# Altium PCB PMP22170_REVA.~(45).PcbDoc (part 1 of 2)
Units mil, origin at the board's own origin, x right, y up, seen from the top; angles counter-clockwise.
Board outline 4950 x 3450 mil, 2 copper layers (Top Layer, Bottom Layer), stack 62 mil thick; 75 components, 28 nets, 160 pads, 77 vias.
Unrouted connection lines stored in the file: 123.
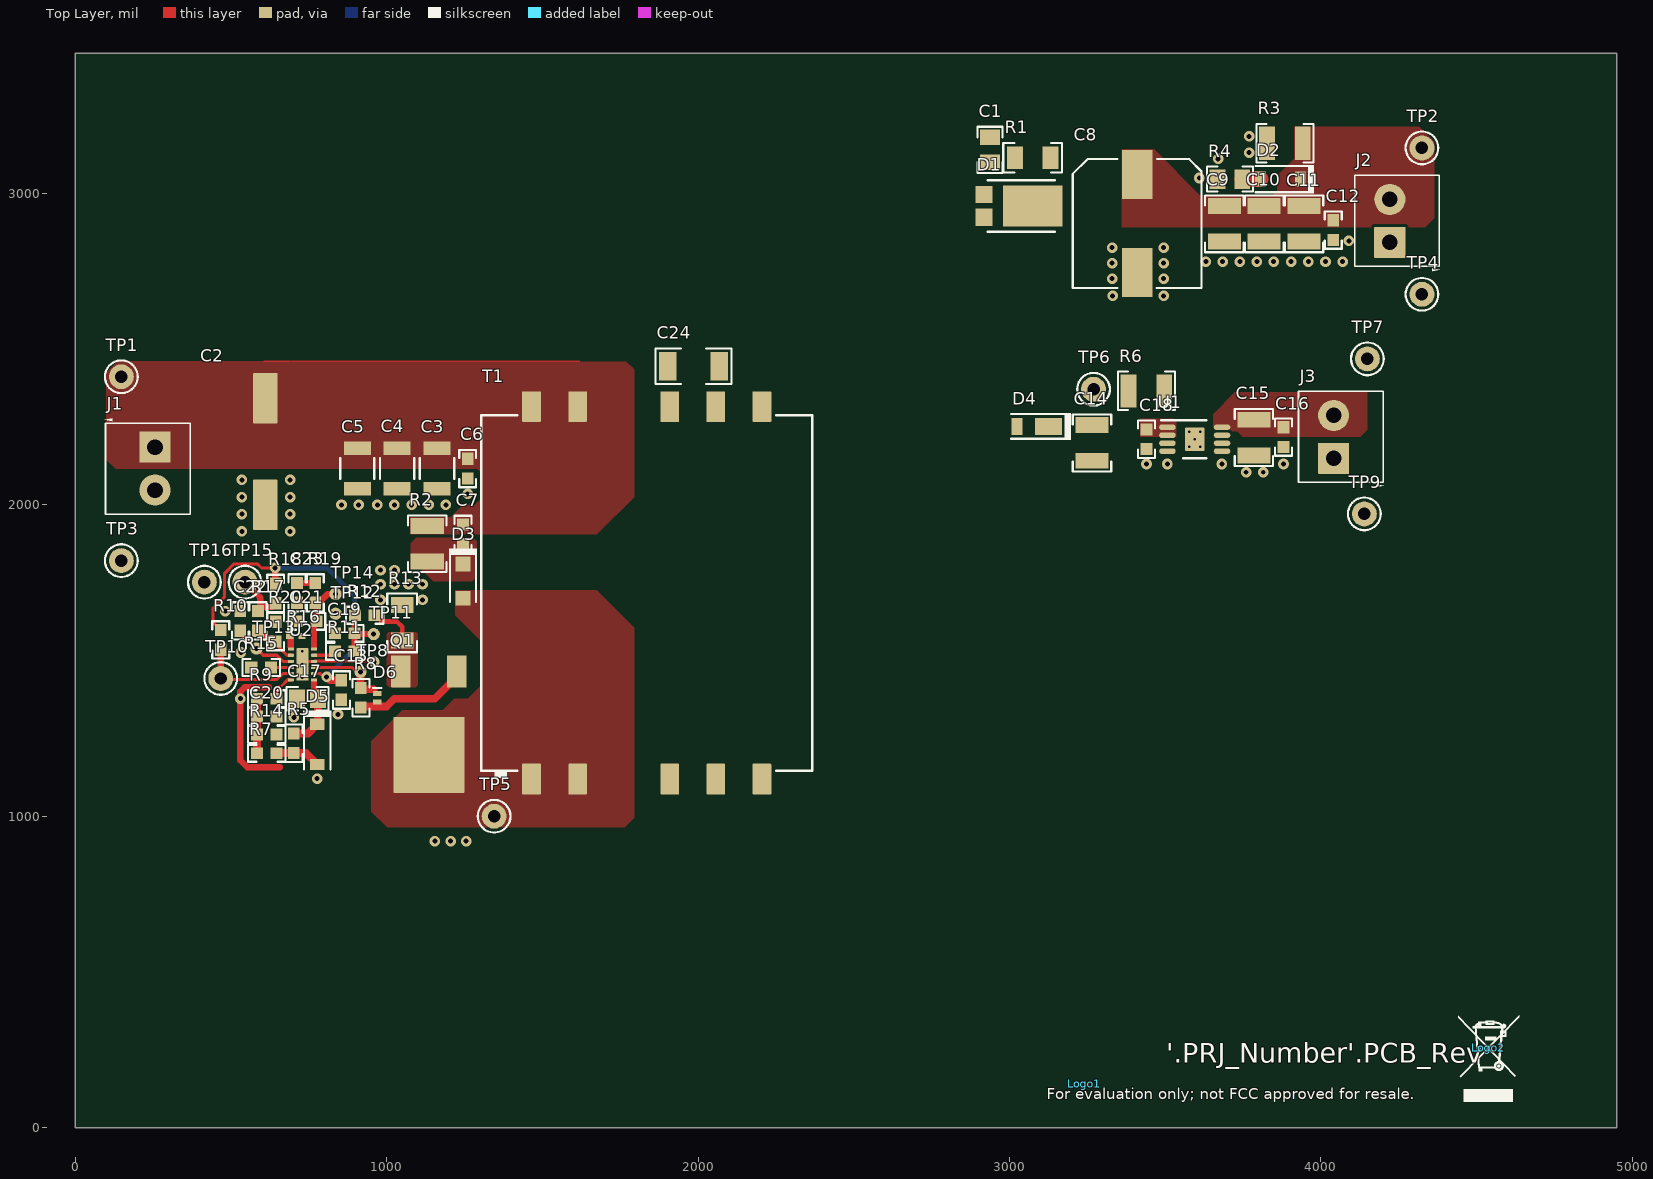
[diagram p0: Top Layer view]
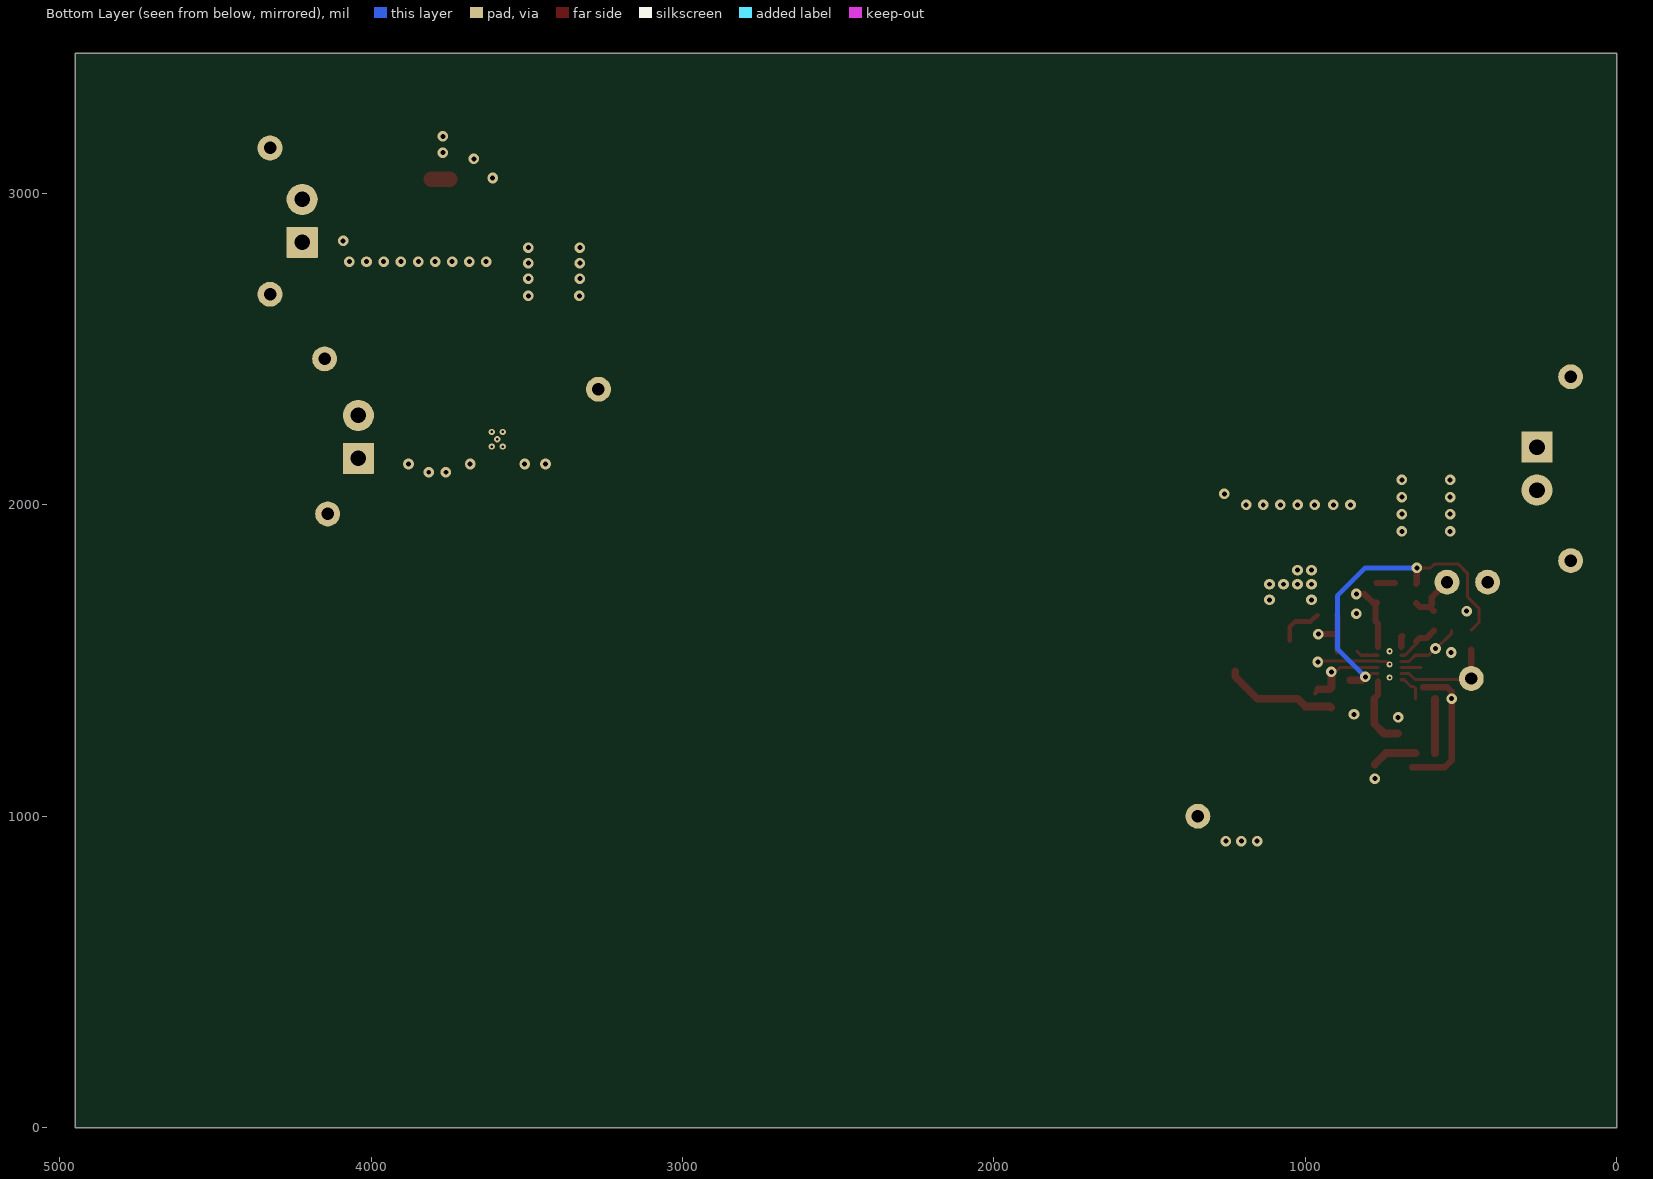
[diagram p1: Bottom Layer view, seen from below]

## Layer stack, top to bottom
Top Solder: solder mask 0.4, Solder Resist, Dk 3.5
Top Layer: signal copper 1.4
Dielectric1: core 59.2, FR-4, Dk 4.8
Bottom Layer: signal copper 1.4
Bottom Solder: solder mask 0.4, Solder Resist, Dk 3.5

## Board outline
0,0 4950,0 4950,3450 0,3450

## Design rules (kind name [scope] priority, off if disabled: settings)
AcuteAngle [All] p1: minimum=4.50000000000000E+0001 checktracksonly=FALSE
AssemblyTestPointUsage [All] p1: valid=2
BoardOutlineClearance BoardOutlineClearance_MountingHoles [OnCopper and InComponentClass('Mounting Holes')] p1: gap=39.37 ignorepadtopadclearanceinfootprint=FALSE
BoardOutlineClearance BoardOutlineClearance_Poly [OnCopper and IsPoly] p2: gap=25 ignorepadtopadclearanceinfootprint=FALSE
BoardOutlineClearance [OnCopper and Not InComponentClass('Logo') and not InComponentClass('FiducialMark') and not InRegion(1000,500,4000,800) and not InPoly] p3: gap=50 ignorepadtopadclearanceinfootprint=FALSE
Clearance Clearance_Keepouts [((IsTrack Or IsArc) And Not InPoly) And IsFree and IsKeepOut vs ((IsTrack Or IsArc) And Not InPoly) And IsFree and IsKeepOut] p1: gap=0 ignorepadtopadclearanceinfootprint=FALSE
Clearance Clearance_Poly [InPolygon] p2: gap=10 ignorepadtopadclearanceinfootprint=TRUE
Clearance Clearance_FiducialMark [IsKeepOut and InComponentClass('FiducialMark') vs IsPad and InComponentClass('FiducialMark')] p3: gap=0 ignorepadtopadclearanceinfootprint=FALSE
Clearance [All] p4: gap=7.87 ignorepadtopadclearanceinfootprint=TRUE
ComponentClearance ComponentClearance_MountingHoles_FiducialMarks [InComponentClass('Mounting Holes') vs InComponentClass('FiducialMark')] p1: gap=50 collisioncheckmode=3 verticalgap=10 showdistances=FALSE
ComponentClearance ComponentClearance_Shunt [InComponentClass('Header') vs InComponentClass('Shunt')] p2: gap=0 collisioncheckmode=3 verticalgap=0 showdistances=FALSE
ComponentClearance ComponentClearance_Logo [InComponentClass('Logo')] p3: gap=50 collisioncheckmode=3 verticalgap=10 showdistances=FALSE
ComponentClearance ComponentClearance_ScrewToNut [(HasFootprint('NY PMS 440 0025 PH')) vs (HasFootprint('Keystone_1902C'))] p4: gap=5 collisioncheckmode=3 verticalgap=10 showdistances=FALSE
ComponentClearance ComponentClearance_MountingHoles [InComponentClass('Mounting Holes')] p5: gap=250 collisioncheckmode=3 verticalgap=100000 showdistances=FALSE
ComponentClearance ComponentClearance_SmallPassives [HasFootprint('0201*') or HasFootprint('0402*') or HasFootprint('0508') or HasFootprint('0603*') or HasFootprint('0612') or HasFootprint('0805*') or HasFootprint('0815*') or HasFootprint('0830*') or HasFootprint('1206*') or HasFootprint('1210*') or HasFootprint('1808*') or HasFootprint('1812*') or HasFootprint('1825*') or HasFootprint('2010*') or HasFootprint('2220*') or HasFootprint('2225*') or HasFootprint('2512*') or HasFootprint('2728*') or HasFootprint('3518*') vs HasFootprint('0201*') or HasFootprint('0402*') or HasFootprint('0508') or HasFootprint('0603*') or HasFootprint('0612') or HasFootprint('0805*') or HasFootprint('0815*') or HasFootprint('0830*') or HasFootprint('1206*') or HasFootprint('1210*') or HasFootprint('1808*') or HasFootprint('1812*') or HasFootprint('1825*') or HasFootprint('2010*') or HasFootprint('2220*') or HasFootprint('2225*') or HasFootprint('2512*') or HasFootprint('2728*') or HasFootprint('3518*')] p6: gap=14.96 collisioncheckmode=3 verticalgap=10 showdistances=FALSE
ComponentClearance ComponentClearance_THtoSMT [IsThruComponent vs IsSMTComponent] p7: gap=30 collisioncheckmode=3 verticalgap=30 showdistances=FALSE
ComponentClearance ComponentClearance_THtoTH [IsThruComponent vs IsThruComponent] p8: gap=30 collisioncheckmode=3 verticalgap=30 showdistances=FALSE
ComponentClearance [All] p9: gap=20 collisioncheckmode=3 verticalgap=10 showdistances=FALSE
DiffPairsRouting [All] p1: maxlimit=100 minlimit=10 mostfreqgap=10 toplayer_minwidth=15 toplayer_maxwidth=15 toplayer_prefwidth=15 bottomlayer_minwidth=15 bottomlayer_maxwidth=15 bottomlayer_prefwidth=15 maxuncoupledlength=1000
FabricationTestPointUsage TestPointUsage [All] p1: valid=2 allowmultiple=FALSE
FabricationTestpoint Testpoint [All] p1: side=3 testpointundercomponent=TRUE minsize=40 maxsize=100 preferedsize=60 minholesize=0 maxholesize=40 preferedholesize=32 testpointgrid=1 allowsidetop=TRUE allowsidebottom=TRUE usegrid=TRUE gridtolerance=0.01
FanoutControl Fanout_LCC [IsLCC] p1: bgadir=Out bgaviamode=Centered fanoutstyle=Auto fanoutdirection=Alternating viagrid=1 // Fanout_LCC (Default Rule)
FanoutControl Fanout_BGA [IsBGA] p2: bgadir=Out bgaviamode=Centered fanoutstyle=Auto fanoutdirection=Alternating viagrid=1 // Fanout_BGA (Default Rule)
FanoutControl Fanout_Default [All] p4: bgadir=Out bgaviamode=Centered fanoutstyle=Auto fanoutdirection=Alternating viagrid=1 // Fanout_Default (Default Rule)
FanoutControl Fanout_Small [(CompPinCount < 5)] p5: bgadir=Out bgaviamode=Centered fanoutstyle=Auto fanoutdirection=OutThenIn viagrid=1 // Fanout_Small (Default Rule)
HoleSize [All] p1: absolutevalues=TRUE maxlimit=251 minlimit=7.87 maxpercent=80.000 minpercent=20.000
MinimumAnnularRing MinimumAnnularRing_ThermalPadVias [IsVia and InAnyComponent] p1: minimumring=5.91
MinimumAnnularRing [All] p2: minimumring=7.87
MinimumSolderMaskSliver MinimumSolderMaskSliver_Logo [InComponentClass('Logo') vs InComponentClass('Logo')] p1: minsoldermaskwidth=0.7
MinimumSolderMaskSliver [All] p2: minsoldermaskwidth=3.94
PlaneClearance [All] p1: clearance=15
PlaneConnect [All] p1: planeconnectstyle=Direct reliefexpansion=10 reliefentries=4 reliefconductorwidth=10 reliefairgap=10
PolygonConnect [All] p1: connectstyle=Direct reliefconductorwidth=10 reliefentries=4 polygonreliefangle="90 Angle" airgapwidth=10
RoutingVias ThermalPadVias [IsVia and InAnyComponent] p1: holewidth=7.87 width=19.68 viastyle="Through Hole" minholewidth=7.87 minwidth=19.68 maxholewidth=12.99 maxwidth=23.62
RoutingVias [All] p2: holewidth=16 width=34 viastyle="Through Hole" minholewidth=7.87 minwidth=26 maxholewidth=40 maxwidth=65
SilkToBoardRegionClearance [Not ((IsComment or IsDesignator) And (Hide <> 'False')) and not InRegion(1000,500,4000,800)] p1:
SilkToSilkClearance SilkToSilkClearance_Pb-FreeLogo [(HasFootprint('Pb-Free_Overlay_Medium') OR HasFootprint('Pb-Free_Overlay_Small')) vs (HasFootprint('Pb-Free_Overlay_Medium') OR HasFootprint('Pb-Free_Overlay_Small'))] p1: silktosilkclearance=0
SilkToSilkClearance [All] p2: silktosilkclearance=0
SilkToSolderMaskClearance SilkToComponentPadClearance [(IsPad or IsFill or IsRegion) and InAnycomponent] p1: minsilkscreentomaskgap=5 clearancetoexposedcopper=TRUE
SilkToSolderMaskClearance "Silk to Solder Mask Opening" [All] p2: minsilkscreentomaskgap=0 clearancetoexposedcopper=FALSE
SolderMaskExpansion [All] p1: expansion=1.97
UnRoutedNet [All] p1: checkbadconnections=TRUE
Width [All] p1: maxlimit=100 minlimit=6 preferedwidth=10 checkconnectedcopper=TRUE
13 further rules are at their usual default settings.

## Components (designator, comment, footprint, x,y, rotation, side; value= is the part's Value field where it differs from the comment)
C1 "Capacitor" 0805_HV 2937.52,3140.12 r270 top value=100pF
C2 "EEH-ZS1H221V" FP-EEHZS1H221P_RADIAL_SMD-MFG 610.24,2171.35 r90 top
C3 "UMK325AB7106KMHT" 1210_280 1161.42,2116.35 r270 top value=10uF
C4 "UMK325AB7106KMHT" 1210_280 1033.46,2116.35 r270 top value=10uF
C5 "UMK325AB7106KMHT" 1210_280 905.51,2116.35 r270 top value=10uF
C6 "Capacitor" 0603 1259.84,2116.35 r270 top value=0.1uF
C7 "Capacitor" 0603 1245,1905 r270 top value=0.1uF
C8 "EEHZC1E331P" SM_RADIAL_10BMM 3409.96,2903.53 r270 top value=330uF
C9 "TMK325B7226KMHT" 1210_270 3690,2902.2 r270 top value=22uF
C10 "TMK325B7226KMHT" 1210_270 3817.95,2902.2 r270 top value=22uF
C11 "TMK325B7226KMHT" 1210_270 3945.91,2902.38 r270 top value=22uF
C12 "Capacitor" 0603 4040,2882.26 r270 top value=0.1uF
C13 "GCM188R71E105KA64D" 0603 854.45,1405.37 r270 top value=1uF
C14 "Capacitor" 1210_270 3265,2198.78 r270 top value=22uF
C15 "Capacitor" 1210_270 3785,2216.22 r270 top value=47uF
C16 "Capacitor" 0603 3880,2217.48 r270 top value=0.1uF
C17 "Capacitor" 0805 745.3,1377.3 r180 top value=1uF
C18 "Capacitor" 0603 3440,2210.79 r270 top value=0.1uF
C19 "Capacitor" 0603 865.22,1587.34 r180 top value=1000pF
C20 "Capacitor" 0603 614.79,1320.34 r0 top value=10pF
C21 "CGA3E2X7R2A222K080AA" 0603 742.84,1625.84 r180 top value=2200pF
C22 "Capacitor" 0603 529.91,1627.22 r90 top value=0.1uF
C23 "CGA3E3X7R1H334K080AB" 0603 711.83,1717.34 r270 top value=0.33uF
C24 "Capacitor" 1808 1985,2445 r180 top value=1000pF
D1 "PDS4200HQ-13" POWERDI5 2996.22,2959.8 r0 top value=200V
D2 "MMSZ5240B-7-F" SOD-123 3870.59,3046.22 r180 top value=10V
D3 "DIODE_SCHOTTKY" SOD-123W 1245,1755 r270 top value=100V
D4 "DFLS1200Q-7" PowerDI123 3074.8,2251.93 r180 top value=200V
D5 "SD103AW-7-F" SOD-123 776.83,1230.84 r270 top value=40V
D6 "DIODE_SCHOTTKY" X1-DFN1006-2 969.37,1380.37 r270 top value=30V
J1 "Receptacle_2x1" TERM_BLK_ED555-2DS 255.91,2185.24 r270 top
J2 "Receptacle_2x1" TERM_BLK_ED555-2DS 4221.5,2842.89 r90 top
J3 "Receptacle_2x1" TERM_BLK_ED555-2DS 4041.18,2149.27 r90 top
Logo1 "FCC disclaimer" FCC_disclaimer 3240,140 r0 top
Logo2 "WEEE logo" WEEE_Minimum 4537.4,255.91 r0 top
Q1 "IPD60N10S4L12ATMA1" DPAK 1135.35,1331.12 r270 top value=100V
R1 "CRCW1206100RFKEAHP" 1206 3074.61,3114.53 r0 top value=100
R2 "ERJ14NF1001U" 1210 1130,1875 r90 top value=1.00k
R3 "ERJ14NF1001U" 1210 3884.76,3161.22 r0 top value=1.00k
R4 "CRCW080580R6FKEA" 0805_HV 3708.19,3046.22 r0 top value=80.6
R5 "Resistor" 0603 701.83,1234.15 r270 top value=0
R6 "ERJ14NF1001U" 1210 3440,2366.22 r180 top value=1.00k
R7 "CRCW0603100KFKEA" 0603 614.79,1202.3 r0 top value=100k
R8 "Resistor" 0603 917.13,1380.37 r90 top value=10.0
R9 "CRCW060371K5FKEA" 0603 614.79,1377.34 r0 top value=71.5k
R10 "CRCW060310K0FKEA" 0603 466.83,1566.19 r270 top value=10.0k
R11 "Resistor" 0603 865.22,1529.66 r0 top value=0
R12 "Resistor" 0603 929.45,1645.37 r0 top value=100
R13 "ERJ-8BWFR010V" 1206 1049.45,1621.18 r270 top value=0.010
R14 "CRCW060324K9FKEA" 0603 614.79,1262.34 r180 top value=24.9k
R15 "CRCW060373K2FKEA" 0603 596.83,1477.49 r0 top value=73.2k
R16 "CRCW04020000Z0ED" 0402L 708.39,1578.99 r180 top value=0
R17 "Resistor" 0603 586.83,1627.34 r270 top value=6.04k
R18 "CRCW060320R0FKEA" 0603 643.33,1715.39 r90 top value=20.0
R19 "CRCW06033K01FKEA" 0603 770.34,1717.34 r270 top value=3.01k
R20 "CRCW06031K00FKEA" 0603 643.33,1592.77 r270 top value=1.00k
T1 "750315862" Wurth_750315862 1835,1717.37 r90 top value=45uH
TP1 "5000" Keystone5000 147.64,2411.42 r90 top
TP2 "5000" Keystone5000 4324.76,3146.22 r90 top
TP3 "5001" Keystone5001 147.64,1820.87 r90 top
TP4 "5001" Keystone5001 4324.76,2676.22 r90 top
TP5 "5002" Keystone5002 1345,1000 r0 top
TP6 "5000" Keystone5000 3270,2371.22 r0 top
TP7 "5000" Keystone5000 4149.45,2468.82 r90 top
TP8 "TP_SM_1MM" TP_SM_1MM 915.97,1463.91 r90 top
TP9 "5001" Keystone5001 4139.61,1970.91 r90 top
TP10 "5000" Keystone5000 466.83,1442.34 r0 top
TP11 "TP_SM_1MM" TP_SM_1MM 958.29,1584.89 r270 top
TP12 "TP_SM_1MM" TP_SM_1MM 835.75,1650.37 r270 top
TP13 "TP_SM_1MM" TP_SM_1MM 581.83,1538.63 r0 top
TP14 "TP_SM_1MM" TP_SM_1MM 835.75,1713.7 r0 top
TP15 "5003" Keystone5003 544.9,1751.78 r0 top
TP16 "5001" Keystone5001 414.45,1751.78 r0 top
U1 "TPS7B8250QDGNRQ1" DGN0008D_N 3595,2210.79 r0 top
U2 "LM5155QDSSTQ1" DSS0012C 729.43,1487.34 r180 top

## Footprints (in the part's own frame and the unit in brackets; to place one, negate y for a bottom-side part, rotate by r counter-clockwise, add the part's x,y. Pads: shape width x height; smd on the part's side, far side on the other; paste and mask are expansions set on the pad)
0402L [mm] "0402 from SM-752 data"
  rect 0.6x0.5 smd: 1(-0.5,0) 2(0.5,0)
  body extent -0.55,-0.3 0.55,0.3, height 0.6
0603 [mm] "0603 from SM-752 data"
  rect 1x0.95 smd: 1(-0.8,0) 2(0.8,0)
  silkscreen extent -1.52,-0.69 1.52,0.69, body extent -0.87,-0.47 0.87,0.47, height 1
0805 [mm] "0805 from SM-752 data"
  rect 1.3x1.5 smd: 1(-0.85,0) 2(0.85,0)
  silkscreen extent -1.72,-0.97 1.72,0.97, body extent -1.1,-0.72 1.1,0.72, height 1.45
0805_HV [mil] "0805 with 30mil clearance between pads"
  rect 50x63 smd: 1(-40,0) 2(40,0)
  silkscreen extent -74,-40 74,40, body extent -43,-29 43,29, height 57
1206 [mm] "1206 from SM-752 data"
  rect 1.3x1.85 smd: 1(-1.45,0) 2(1.45,0)
  silkscreen extent -2.4,-1.21 2.4,1.21, body extent -1.7,-0.9 1.7,0.9, height 1.35
1210 [mm] "1210 from SM-752 data"
  rect 1.3x2.7 smd: 1(-1.45,0) 2(1.45,0)
  silkscreen extent -2.32,-1.57 2.32,1.57, body extent -1.7,-1.35 1.7,1.35, height 1.35
1210_270 [mm] "1210"
  rect 1.3x2.7 smd: 1(-1.45,0) 2(1.45,0)
  silkscreen extent -2.32,-1.57 2.32,1.57, body extent -1.7,-1.35 1.7,1.35, height 2.7
1210_280 [mm] "SMD, 2-Leads, Body 3.6x2.8mm, Height 2.8mm"
  rect 1.1x2.2 smd: 1(-1.65,0) 2(1.65,0)
  silkscreen extent -0.84,-1.4 0.84,1.4, body extent -1.8,-1.4 1.8,1.4, height 2.8
1808 [mm] "Chip Capacitor, Body 4.6x2.0mm, IPC Medium Density"
  rect 1.4x2.3 smd: 1(-2.1,0) 2(2.1,0)
  silkscreen extent -3.1,-1.45 3.1,1.45, body extent -2.47,-1.2 2.47,1.2, height 2.03
DGN0008D_N [mm] "TSOP, 8-Leads, Body 3x3mm, Pitch 0.65mm, Thermal Pad 1.89x1.57mm, IPC Medium Density"
  rrect100% 1.35x0.45 smd: 1(-2.225,0.975) 2(-2.225,0.325) 3(-2.225,-0.325) 4(-2.225,-0.975) 5(2.225,-0.975) 6(2.225,-0.325) 7(2.225,0.325) 8(2.225,0.975)
  rrect6% 1.57x1.89 smd: 9(0,0)
  silkscreen extent -2.73,-1.55 0.95,1.55, body extent -2.46,-1.5 2.46,1.5, height 1.1
DPAK [mm] "D-PAK, 3-Pads, Body 6.22x6.73mm (max), TO-252AA using nominal STEP model"
  rrect6% 2.6x1.6 smd: 1(-3.4,2.28) 3(-3.4,-2.28)
  rrect2% 6.2x5.8 smd paste-3: 2(3.4,0)
  body extent -3.86,-3.29 5.84,3.29, height 2.48
DSS0012C [mm] "WSON-12"
  rrect40% 0.5x0.25 smd: 1(-0.95,1.25) 2(-0.95,0.75) 3(-0.95,0.25) 4(-0.95,-0.25) 5(-0.95,-0.75) 6(-0.95,-1.25) 7(0.95,-1.25) 8(0.95,-0.75) 9(0.95,-0.25) 10(0.95,0.25) 11(0.95,0.75) 12(0.95,1.25)
  rrect11% 0.95x1.17 on Top Paste: 13(0,0.685) 13(0,-0.685)
  rrect11% 1x2.65 smd paste-0.5: 13(0,0)
  body extent -1,-1.5 1,1.5, height 0.81
FCC_disclaimer [mil]
FP-EEHZS1H221P_RADIAL_SMD-MFG [mm]
  rrect5% 4.1x2 smd paste+0 mask+0: 1(-4.35,0) 2(4.35,0)
  body extent -6.65,-5.5 6.65,5.5, height 0.25
Keystone5000 [mil] "For Keystone 500x miniature loop terminals"
  round 80 hole 40: 1(0,0)
  silkscreen extent -52,-52 52,52, body extent -49,-49 49,49, height 182
Keystone5001 [mil] "For Keystone 500x miniature loop terminals"
  round 80 hole 40: 1(0,0)
  silkscreen extent -52,-52 52,52, body extent -49,-49 49,49, height 182
Keystone5002 [mil] "For Keystone 500x miniature loop terminals"
  round 80 hole 40: 1(0,0)
  silkscreen extent -52,-52 52,52, body extent -49,-49 49,49, height 182
Keystone5003 [mil] "For Keystone 500x miniature loop terminals"
  round 80 hole 40: 1(0,0)
  silkscreen extent -52,-52 52,52, body extent -49,-49 49,49, height 182
POWERDI5 [mm] "Diodes Inc recommended land pattern, ap02001.pdf rev 60"
  rect 1.4x1.39 smd: 1(-1.991,0.92) 2(-1.991,-0.92)
  rect 4.86x3.36 smd: 3(1.991,0)
  silkscreen extent -1.7,-2.1 3.8,2.1, body extent -2.27,-2.03 4.33,2.03, height 1.17
PowerDI123 [mm] "Diodes Inc recommended land pattern, document number DS30628 Rev. 6-2"
  rect 2.2x1.4 smd: 1(-1.275,0)
  rect 0.9x1.4 smd: 2(1.275,0)
  silkscreen extent -3.1,-1.09 1.76,1.09, body extent -2.38,-0.97 1.52,0.96, height 1
SM_RADIAL_10BMM [mm] "Nichicon 10x10"
  rect 4x2.5 smd: 1(-4,0) 2(4,0)
  silkscreen extent -5.25,-5.25 5.25,5.25, body extent -5.25,-5.25 5.25,5.25, height 10.5
SOD-123 [mm] "On Semi recommended land pattern"
  rect 0.915x1.22 smd: 1(-1.637,0) 2(1.637,0)
  silkscreen extent -2.74,-1.17 2.03,1.17, body extent -1.93,-0.9 1.93,0.9, height 1.35
SOD-123W [mm] "NXP recommended land pattern"
  rect 1.2x1.2 smd paste-0.05: 1(-1.4,0) 2(1.4,0)
  silkscreen extent -2.64,-1.14 1.68,1.14, body extent -1.85,-0.95 1.85,0.95, height 1.1
TERM_BLK_ED555-2DS [mil]
  rrect4% 100x100 hole 50: 1(0,0)
  round 100 hole 50: 2(138,0)
  silkscreen extent -93,-161 215,113, body extent -69,-150 207,106, height 323
TP_SM_1MM [mm] "1mm Test Point, SMT"
  round 1 smd paste-0.5: 1(0,0)
WEEE_Minimum [mil] "WEEElie bin"
  silkscreen extent -95,-172 99,104
Wurth_750315862 [mm] "SMD, 12-Leads, Body 32.45x27.03mm, Pitch 3.76mm"
  rrect7% 2.5x1.52 smd: 1(-15.19,9.4) 2(-15.19,5.64) 4(-15.19,-1.88) 5(-15.19,-5.64) 6(-15.19,-9.4) 7(15.19,-9.4) 8(15.19,-5.64) 9(15.19,-1.88) 11(15.19,5.64) 12(15.19,9.4)
  silkscreen extent -15.1,-13.51 14.5,13.51, body extent -16.25,-13.51 16.25,13.51, height 13.98
X1-DFN1006-2 [mm] "DIODES, INC"
  rect 0.4x0.7 smd: 1(-0.35,0) 2(0.35,0)
  silkscreen extent -0.8,-0.35 -0.8,0.35, body extent -0.54,-0.34 0.54,0.34, height 0.53

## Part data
C1: library part CMP-0008236-2, "CAP, CERM, 100 pF, 250 V, +/- 5%, C0G/NP0, 0805", Cap_Case=0805, Manufacturer=MuRata, PartNumber=GRM21A5C2E101JW01D, Supplier Part Number 1=490-5542-1-ND, TempCo=C0G/NP0, Tolerance_%=5%, Value1=Unknown, Value2=250V, ValueDisplayed=100pF
C2: library part CMP-0087071-1, "220µF 50V Aluminum Polymer Capacitor Radial, Can - SMD 13 mOhm 4000 Hrs @ 125°C", Manufacturer=Panasonic, Tolerance_%=20%
C3 C4 C5: library part CMP-0009258-2, "CAP, CERM, 10 uF, 50 V, +/- 10%, X7R, AEC-Q200 Grade 1, 1210", Cap_Case=1210, Manufacturer="Taiyo Yuden", Supplier Part Number 1=587-4326-1-ND, TempCo=X7R, Tolerance_%=10%, Value1=Unknown, Value2=50V, ValueDisplayed=10uF
C6 C7 C12: library part CMP-0007144-4, "CAP, CERM, 0.1 uF, 50 V, +/- 10%, X7R, 0603", Cap_Case=0603, Manufacturer=MuRata, PartNumber=GCM188R71H104KA57D, Supplier Part Number 1=490-4779-1-ND, TempCo=X7R, Tolerance_%=10%, Value1="0.02 ohm", Value2=50V, ValueDisplayed=0.1uF
C8: library part CMP-0012593-3, "CAP, Polymer Hybrid, 330 uF, 25 V, +/- 20%, 20 mohm, 10x10 SMD", Manufacturer=Panasonic, Supplier Part Number 1=P15459CT-ND, Tolerance_%=20%, Value1="20 ohm", Value2=25V, ValueDisplayed=330uF
C9 C10 C11: library part CMP-0009255-2, "CAP, CERM, 22 uF, 25 V, +/- 10%, X7R, AEC-Q200 Grade 1, 1210", Cap_Case=1210, Manufacturer="Taiyo Yuden", Supplier Part Number 1=587-4337-1-ND, TempCo=X7R, Tolerance_%=10%, Value1=Unknown, Value2=25V, ValueDisplayed=22uF
C13: library part CMP-0007139-4, "CAP, CERM, 1 uF, 25 V, +/- 10%, X7R, AEC-Q200 Grade 1, 0603", Cap_Case=0603, Manufacturer=MuRata, Supplier Part Number 1=490-10673-1-ND, TempCo=X7R, Tolerance_%=10%, Value1=Unknown, Value2=25V, ValueDisplayed=1uF
C14: library part CMP-0009224-2, "CAP, CERM, 22 uF, 25 V, +/- 10%, X7R, 1210", Cap_Case=1210, Manufacturer=MuRata, PartNumber=GRM32ER71E226KE15L, Supplier Part Number 1=490-5313-1-ND, TempCo=X7R, Tolerance_%=10%, Value1=Unknown, Value2=25V, ValueDisplayed=22uF
C15: library part CMP-0009220-2, "CAP, CERM, 47 uF, 10 V, +/- 10%, X7R, 1210", Cap_Case=1210, Manufacturer=MuRata, PartNumber=GRM32ER71A476KE15L, Supplier Part Number 1=490-5312-1-ND, TempCo=X7R, Tolerance_%=10%, Value1=Unknown, Value2=10V, ValueDisplayed=47uF
C16 C18 C22: library part CMP-0007378-5, "CAP, CERM, 0.1 uF, 16 V, +/- 10%, X7R, 0603", Cap_Case=0603, Manufacturer=MuRata, PartNumber=GRM188R71C104KA01D, Supplier Part Number 1=490-1532-1-ND, TempCo=X7R, Tolerance_%=10%, Value1=Unknown, Value2=16V, ValueDisplayed=0.1uF
C17: library part CMP-0008350-2, "CAP, CERM, 1 uF, 50 V, +/- 10%, X7R, 0805", Cap_Case=0805, Manufacturer=MuRata, PartNumber=GRM21BR71H105KA12L, Supplier Part Number 1=490-4736-1-ND, TempCo=X7R, Tolerance_%=10%, Value1=Unknown, Value2=50V, ValueDisplayed=1uF
C19: library part CMP-0007402-4, "CAP, CERM, 1000 pF, 25 V, +/- 10%, X7R, 0603", Cap_Case=0603, Manufacturer=MuRata, PartNumber=GRM188R71E102KA01D, Supplier Part Number 1=GRM188R71E102KA01D-ND, TempCo=X7R, Tolerance_%=10%, Value1=Unknown, Value2=25V, ValueDisplayed=1000pF
C20: library part CMP-0007170-4, "CAP, CERM, 10 pF, 50 V, +/- 5%, C0G/NP0, 0603", Cap_Case=0603, Manufacturer=MuRata, PartNumber=GRM1885C1H100JA01D, Supplier Part Number 1=490-1403-1-ND, TempCo=C0G/NP0, Tolerance_%=5%, Value1=Unknown, Value2=50V, ValueDisplayed=10pF
C21: library part CMP-0007085-4, "CAP, CERM, 2200 pF, 100 V, +/- 10%, X7R, AEC-Q200 Grade 1, 0603", Cap_Case=0603, Manufacturer=TDK, Supplier Part Number 1=445-5808-1-ND, TempCo=X7R, Tolerance_%=10%, Value1="0.923948 ohm", Value2=100V, ValueDisplayed=2200pF
C23: library part CMP-0007095-4, "CAP, CERM, 0.33 uF, 50 V, +/- 10%, X7R, AEC-Q200 Grade 1, 0603", Cap_Case=0603, Manufacturer=TDK, Supplier Part Number 1=445-174426-1-ND, TempCo=X7R, Tolerance_%=10%, Value1="0.01584 ohm", Value2=50V, ValueDisplayed=0.33uF
C24: library part CMP-0009436-2, "CAP, CERM, 1000 pF, 2000 V, +/- 10%, X7R, 1808", Cap_Case=1808, Manufacturer=MuRata, PartNumber=GR442QR73D102KW01L, Supplier Part Number 1=490-8145-1-ND, TempCo=X7R, Tolerance_%=10%, Value1=Unknown, Value2=2000V, ValueDisplayed=1000pF
D1: library part CMP-0081019-2, "Diode, Schottky, 200 V, 4 A, AEC-Q101, PowerDI5", Manufacturer="Diodes Inc.", Value1=4A, Value2=0.84V
D2: library part CMP-0005749-3, "Diode, Zener, 10 V, 500 mW, SOD-123", Manufacturer="Diodes Inc.", Power_W=500mW, Value1=0.5W
D3: library part CMP-0028782-2, "Diode, Schottky, 100 V, 1 A, AEC-Q101, SOD-123W", Manufacturer=Nexperia, PartNumber=PMEG10010ELRX, Value1=1A, Value2=0.77V
D4: library part CMP-0028517-2, "Diode, Schottky, 200 V, 1 A, PowerDI123", Manufacturer="Diodes Inc.", Value1=1A, Value2=0.85V
D5: library part CMP-0028543-1, "Diode, Schottky, 40 V, 0.35 A, SOD-123", Manufacturer="Diodes Inc.", Supplier Part Number 1=SD103-AWDICT-ND, Value1=0.35A, Value2=0.55V
D6: library part CMP-0076931-2, "Diode, Schottky, 30 V, 0.2 A, 1.00x0.50x0.60mm", Manufacturer="Diodes Inc.", PartNumber=BAT54LP-7, Value1=0.2A, Value2=1V
J1 J2 J3: library part CMP-0074913-1, "Terminal Block, 3.5mm Pitch, 2x1, TH", Color=Grey, Current_A=6A, Manufacturer="On-Shore Technology", PartNumber=ED555/2DS, Supplier Part Number 1=ED1514-ND, Voltage_V=150V
Logo1: library part CMP-0074847-1, "FCC_disclaimer"
Logo2: library part CMP-0074769-1
Q1: library part CMP-0080670-2, "MOSFET, N-CH, 100 V, 60 A, AEC-Q101, DPAK", Alternate Manufacturer=None, Manufacturer="Infineon Technologies", Supplier Part Number 1=IPD60N10S4L12ATMA1CT-ND, Value1="0.015 ohm", Value2="38 nC"
R1: library part CMP-0016570-3, "RES, 100, 1%, 0.5 W, AEC-Q200 Grade 0, 1206", Manufacturer=Vishay-Dale, Power_W=500mW, Supplier Part Number 1=541-100UCT-ND, TempCo="100 ppm/C", Tolerance_%=1%, Value2=0.5W, Value_Code=100R, ValueDisplayed=100
R2 R3 R6: library part CMP-0015030-3, "RES, 1.00 k, 1%, 0.5 W, AEC-Q200 Grade 0, 1210", Manufacturer=Panasonic, Power_W=500mW, Supplier Part Number 1=P1.00KAACT-ND, TempCo="100 ppm/C", Tolerance_%=1%, Value2=0.5W, Value_Code=1k00, ValueDisplayed=1.00k
R4: library part CMP-0021452-3, "RES, 80.6, 1%, 0.125 W, AEC-Q200 Grade 0, 0805", Manufacturer=Vishay-Dale, Power_W=125mW, Supplier Part Number 1=541-80.6CCT-ND, TempCo="100 ppm/C", Tolerance_%=1%, Value2=0.125W, Value_Code=80R6, ValueDisplayed=80.6
R5 R11: library part CMP-0025697-4, "RES, 0, 5%, 0.1 W, AEC-Q200 Grade 0, 0603", Manufacturer=Vishay-Dale, PartNumber=CRCW06030000Z0EA, Power_W=100mW, Supplier Part Number 1=541-0.0GCT-ND, TempCo="200 ppm/C", Tolerance_%=5%, Value2=0.1W, Value_Code=0000, ValueDisplayed=0
R7: library part CMP-0021990-4, "RES, 100 k, 1%, 0.1 W, AEC-Q200 Grade 0, 0603", Manufacturer=Vishay-Dale, Power_W=100mW, Supplier Part Number 1=541-100KHCT-ND, TempCo="100 ppm/C", Tolerance_%=1%, Value2=0.1W, Value_Code=100k
R8: library part CMP-0022003-4, "RES, 10.0, 1%, 0.1 W, AEC-Q200 Grade 0, 0603", Manufacturer=Vishay-Dale, PartNumber=CRCW060310R0FKEA, Power_W=100mW, Supplier Part Number 1=541-10.0HCT-ND, TempCo="100 ppm/C", Tolerance_%=1%, Value2=0.1W, Value_Code=10R0, ValueDisplayed=10.0
R9: library part CMP-0022581-4, "RES, 71.5 k, 1%, 0.1 W, AEC-Q200 Grade 0, 0603", Manufacturer=Vishay-Dale, Power_W=100mW, Supplier Part Number 1=541-71.5KHCT-ND, TempCo="100 ppm/C", Tolerance_%=1%, Value2=0.1W, Value_Code=71k5, ValueDisplayed=71.5k
R10: library part CMP-0021998-4, "RES, 10.0 k, 1%, 0.1 W, AEC-Q200 Grade 0, 0603", Manufacturer=Vishay-Dale, Power_W=100mW, Supplier Part Number 1=541-10.0KHCT-ND, TempCo="100 ppm/C", Tolerance_%=1%, Value2=0.1W, Value_Code=10k0, ValueDisplayed=10.0k
R12: library part CMP-0021991-4, "RES, 100, 1%, 0.1 W, AEC-Q200 Grade 0, 0603", Manufacturer=Vishay-Dale, PartNumber=CRCW0603100RFKEA, Power_W=100mW, Supplier Part Number 1=541-100HCT-ND, TempCo="100 ppm/C", Tolerance_%=1%, Value2=0.1W, Value_Code=100R, ValueDisplayed=100
R13: library part CMP-0750151-1, "RES, 0.010, 1%, 1 W, AEC-Q200 Grade 0, 1206", Manufacturer=Panasonic, Power_W=1W, TempCo="200 ppm/C", Tolerance_%=1%, Value_Code=R010, ValueDisplayed=0.010
R14: library part CMP-0022237-4, "RES, 24.9 k, 1%, 0.1 W, AEC-Q200 Grade 0, 0603", Manufacturer=Vishay-Dale, Power_W=100mW, Supplier Part Number 1=541-24.9KHCT-ND, TempCo="100 ppm/C", Tolerance_%=1%, Value2=0.1W, Value_Code=24k9, ValueDisplayed=24.9k
R15: library part CMP-0022585-4, "RES, 73.2 k, 1%, 0.1 W, AEC-Q200 Grade 0, 0603", Manufacturer=Vishay-Dale, Power_W=100mW, Supplier Part Number 1=541-73.2KHCT-ND, TempCo="100 ppm/C", Tolerance_%=1%, Value2=0.1W, Value_Code=73k2, ValueDisplayed=73.2k
R16: library part CMP-0026822-3, "RES, 0, 5%, 0.063 W, AEC-Q200 Grade 0, 0402", Manufacturer=Vishay-Dale, Power_W=63mW, Supplier Part Number 1=541-0.0JCT-ND, TempCo="200 ppm/C", Tolerance_%=5%, Value2=0.063W, Value_Code=0000, ValueDisplayed=0
R17: library part CMP-0022558-4, "RES, 6.04 k, 1%, 0.1 W, AEC-Q200 Grade 0, 0603", Manufacturer=Vishay-Dale, PartNumber=CRCW06036K04FKEA, Power_W=100mW, Supplier Part Number 1=541-6.04KHCT-ND, TempCo="100 ppm/C", Tolerance_%=1%, Value2=0.1W, Value_Code=6k04, ValueDisplayed=6.04k
R18: library part CMP-0022206-4, "RES, 20.0, 1%, 0.1 W, AEC-Q200 Grade 0, 0603", Manufacturer=Vishay-Dale, Power_W=100mW, Supplier Part Number 1=541-20.0HCT-ND, TempCo="100 ppm/C", Tolerance_%=1%, Value2=0.1W, Value_Code=20R0, ValueDisplayed=20.0
R19: library part CMP-0022371-4, "RES, 3.01 k, 1%, 0.1 W, AEC-Q200 Grade 0, 0603", Manufacturer=Vishay-Dale, Power_W=100mW, Supplier Part Number 1=541-3.01KHCT-ND, TempCo="100 ppm/C", Tolerance_%=1%, Value2=0.1W, Value_Code=3k01, ValueDisplayed=3.01k
R20: library part CMP-0022109-5, "RES, 1.00 k, 1%, 0.1 W, AEC-Q200 Grade 0, 0603", Manufacturer=Vishay-Dale, Power_W=100mW, Supplier Part Number 1=541-1.00KHCT-ND, TempCo="100 ppm/C", Tolerance_%=1%, Value2=0.1W, Value_Code=1k00, ValueDisplayed=1.00k
T1: library part CMP-0030646-1, "Transformer, 45 uH, SMT", Manufacturer="Wurth Elektronik", ValueDisplayed=45uH
TP1 TP2 TP6 TP7 TP10: library part CMP-0055137-1, "Test Point, Miniature, Red, TH", Color=Red, Manufacturer=Keystone, Supplier Part Number 1=36-5000-ND
TP3 TP4 TP9 TP16: library part CMP-0055138-1, "Test Point, Miniature, Black, TH", Color=Black, Manufacturer=Keystone, Supplier Part Number 1=36-5001-ND
TP5: library part CMP-0055139-1, "Test Point, Miniature, White, TH", Color=White, Manufacturer=Keystone, Supplier Part Number 1=36-5002-ND
TP8 TP11 TP12 TP13 TP14: library part CMP-0003825-1, "1mm Test Point, SMT", Manufacturer=Any
TP15: library part CMP-0055140-1, "Test Point, Miniature, Orange, TH", Color=Orange, Manufacturer=Keystone, Supplier Part Number 1=36-5003-ND
U1: library part CMP-0013313-4, "300mA High-Voltage Ultra-Low-Iq Low-Dropout (LDO) Regulator, DGN0008D (VSSOP-8)", Alternate Manufacturer="Texas Instruments"
U2: library part CMP-0081538-1, "Automotive Grade 2.2-MHz Wide Input Non-synchronous Boost Controller, DSS0012C (WSON-12)", Alternate Manufacturer="Texas Instruments", Alternate PartNumber=LM5155QDSSRQ1

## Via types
v1: diameter 34, hole 16, Top Layer to Bottom Layer, 69 vias
v2: diameter 19.68, hole 7.87, Top Layer to Bottom Layer, 8 vias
